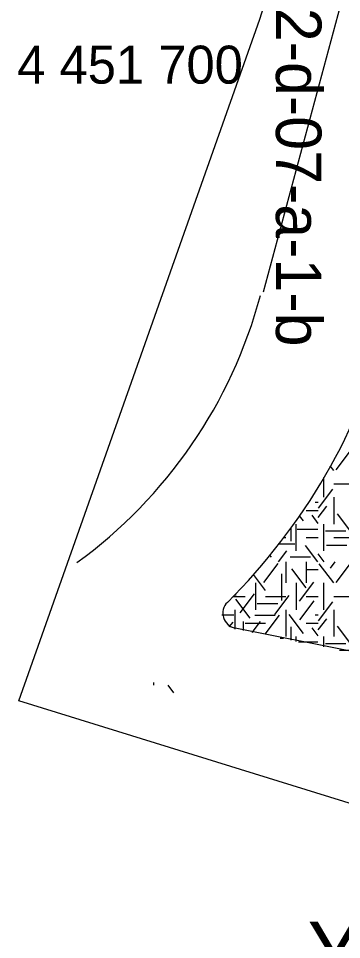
# Model space of a CAD drawing. Extents: x 419677 to 421689, y 4450851 to 4452923.
# Drawn here: x 420147 to 420168.3, y 4451828.2 to 4451888.8 of the extents above; entities that cross this region are included whole.
import ezdxf

# ---------------------------------------------------------------- set-up
doc = ezdxf.new("R2010")
doc.units = 0
for name, color, linetype in [('_TASARIM', 7, 'Continuous'), ('AA_HH', 7, 'Continuous'), ('Level 1', 7, 'Continuous'), ('Level 15', 7, 'Continuous'), ('Level 41', 7, 'Continuous')]:
    doc.layers.add(name, color=color, linetype=linetype)

# ---------------------------------------------------------------- blocks, each defined once
blk = doc.blocks.new('YA')
at = {"layer": 'Level 41'}
blk.add_text('Y.A.', height=4, dxfattribs=at).set_placement((-5.166, -2))

msp = doc.modelspace()

# ---------------------------------------------------------------- linework, layer by layer
at = {"layer": '_TASARIM'}
msp.add_line((420186.468, 4451957.55), (420163.098, 4451870.768), dxfattribs=at)
msp.add_arc((420132.014, 4451878.853), 32, 305.99132, 344.92793, dxfattribs=at)
at = {"layer": 'Level 1'}
msp.add_line((420168.962, 4451847.103), (420161.238, 4451848.656), dxfattribs=at)
msp.add_line((420168.962, 4451847.103), (420161.238, 4451848.656), dxfattribs=at)
msp.add_line((420168.962, 4451847.103), (420161.238, 4451848.656), dxfattribs=at)
for centre, radius, start, end in [((420132.199, 4451879.089), 40.5, 314.78901, 344.92793), ((420132.199, 4451879.089), 40.5, 314.78901, 344.92793), ((420132.199, 4451879.089), 40.5, 314.78901, 344.92793), ((420161.435, 4451849.636), 1, 134.78901, 258.63401), ((420161.435, 4451849.636), 1, 134.78901, 258.63401), ((420161.435, 4451849.636), 1, 134.78901, 258.63401)]:
    msp.add_arc(centre, radius, start, end, dxfattribs=at)
at = {"layer": 'Level 15'}
msp.add_lwpolyline([(420240.251, 4451968.677), (420239.949, 4451966.602), (420239.949, 4451966.602), (420231.732, 4451917.739), (420240.801, 4451915.152), (420236.082, 4451892.337), (420229.855, 4451894.289), (420220.346, 4451839.788), (420214.729, 4451827.789), (420207.555, 4451825.12), (420146.986, 4451843.868), (420162.882, 4451888.718), (420178.991, 4451939.954), (420183.444, 4451958.583), (420204.023, 4451977.132), (420216.413, 4451977.263), (420240.251, 4451968.677)], dxfattribs=at)
at = {"layer": 'Level 41'}
for p, q in [((420167.902, 4451859.067), (420168.851, 4451860.317)), ((420167.742, 4451859.032), (420167.517, 4451859.328)), ((420167.083, 4451857.265), (420167.083, 4451858.567)), ((420167.754, 4451858.148), (420169.097, 4451858.148)), ((420166.731, 4451856.544), (420167.68, 4451857.793)), ((420166.517, 4451856.941), (420166.721, 4451856.941)), ((420167.754, 4451857.265), (420167.754, 4451855.498)), ((420165.933, 4451856.381), (420166.721, 4451856.381)), ((420166.721, 4451855.935), (420167.28, 4451856.671)), ((420168.941, 4451854.93), (420167.992, 4451856.18)), ((420165.747, 4451855.701), (420165.481, 4451856.05)), ((420166.721, 4451855.541), (420166.315, 4451856.075)), ((420164.908, 4451855.24), (420164.908, 4451854.375)), ((420165.262, 4451853.73), (420165.262, 4451855.498)), ((420165.344, 4451855.155), (420166.687, 4451855.155)), ((420167.083, 4451853.73), (420167.083, 4451855.498)), ((420167.206, 4451855.049), (420168.549, 4451855.049)), ((420164.444, 4451854.614), (420164.59, 4451854.614)), ((420165.933, 4451854.614), (420166.721, 4451854.614)), ((420167.754, 4451854.614), (420169.097, 4451854.614)), ((420164.109, 4451853.021), (420164.646, 4451853.727)), ((420164.132, 4451854.207), (420165.169, 4451854.207)), ((420166.692, 4451853.021), (420165.89, 4451854.077)), ((420167.26, 4451854.103), (420168.602, 4451854.103)), ((420163.643, 4451853.319), (420163.537, 4451853.458)), ((420164.865, 4451853.333), (420166.208, 4451853.333)), ((420167.115, 4451853.021), (420166.721, 4451853.539)), ((420163.137, 4451851.658), (420164.086, 4451852.908)), ((420164.59, 4451853.021), (420164.59, 4451851.623)), ((420165.934, 4451851.307), (420164.985, 4451852.556)), ((420165.933, 4451853.021), (420165.933, 4451851.623)), ((420165.933, 4451853.021), (420165.933, 4451851.623)), ((420165.933, 4451852.507), (420166.721, 4451852.507)), ((420167.742, 4451851.623), (420166.793, 4451852.873)), ((420167.531, 4451852.604), (420167.848, 4451853.021)), ((420167.902, 4451851.658), (420168.851, 4451852.908)), ((420163.244, 4451851.132), (420162.449, 4451852.177)), ((420164.308, 4451852.233), (420164.308, 4451850.466)), ((420162.576, 4451851.623), (420162.576, 4451849.856)), ((420165.262, 4451851.623), (420165.262, 4451849.856)), ((420165.262, 4451851.623), (420165.262, 4451849.856)), ((420165.482, 4451850.43), (420166.431, 4451851.68)), ((420167.083, 4451849.856), (420167.083, 4451851.623)), ((420161.111, 4451850.739), (420161.904, 4451850.739)), ((420161.26, 4451850.892), (420161.26, 4451850.787)), ((420161.566, 4451849.66), (420162.517, 4451850.909)), ((420163.247, 4451850.739), (420164.59, 4451850.739)), ((420163.857, 4451849.555), (420164.806, 4451850.805)), ((420165.933, 4451850.739), (420166.721, 4451850.739)), ((420167.754, 4451850.739), (420169.097, 4451850.739)), ((420162.232, 4451849.31), (420161.282, 4451850.559)), ((420162.707, 4451850.269), (420164.05, 4451850.269)), ((420165.508, 4451849.204), (420166.458, 4451850.453)), ((420166.731, 4451849.135), (420167.68, 4451850.384)), ((420160.372, 4451849.532), (420161.148, 4451849.532)), ((420161.233, 4451849.856), (420161.233, 4451848.589)), ((420162.547, 4451849.499), (420163.89, 4451849.499)), ((420163.217, 4451848.258), (420164.167, 4451849.508)), ((420164.59, 4451849.856), (420164.59, 4451848.089)), ((420165.747, 4451848.292), (420164.798, 4451849.541)), ((420166.517, 4451849.532), (420166.721, 4451849.532)), ((420167.754, 4451849.856), (420167.754, 4451848.089)), ((420160.855, 4451848.725), (420161.104, 4451849.052)), ((420161.765, 4451849.084), (420161.765, 4451848.482)), ((420161.904, 4451848.972), (420163.247, 4451848.972)), ((420162.363, 4451848.362), (420162.914, 4451849.087)), ((420165.933, 4451848.972), (420166.721, 4451848.972)), ((420166.721, 4451848.526), (420167.28, 4451849.262)), ((420164.908, 4451848.734), (420164.908, 4451847.85)), ((420166.721, 4451848.132), (420166.315, 4451848.666)), ((420168.941, 4451847.521), (420167.992, 4451848.771)), ((420164.208, 4451847.991), (420164.424, 4451847.991)), ((420165.262, 4451847.779), (420165.262, 4451848.089)), ((420165.427, 4451847.746), (420166.687, 4451847.746)), ((420167.083, 4451847.413), (420167.083, 4451848.089)), ((420167.206, 4451847.64), (420168.549, 4451847.64)), ((420168.119, 4451847.205), (420169.097, 4451847.205)), ((420155.861, 4451845.061), (420155.861, 4451844.889)), ((420157.201, 4451844.398), (420156.82, 4451844.9))]:
    msp.add_line(p, q, dxfattribs=at)

# ---------------------------------------------------------------- block references
msp.add_blockref('YA', (420171.188, 4451827.336), dxfattribs=at)
msp.add_blockref('YA', (420171.188, 4451827.336), dxfattribs=at)

# ---------------------------------------------------------------- texts
at = {"layer": 'AA_HH'}
msp.add_text('BURSA-H22-d-07-a-1-b', height=3, rotation=270, dxfattribs=at).set_placement((420163.932, 4451909.764))
msp.add_text('4 451 700', height=2.5, dxfattribs=at).set_placement((420146.882, 4451884.485))

doc.saveas('drawing.dxf')
